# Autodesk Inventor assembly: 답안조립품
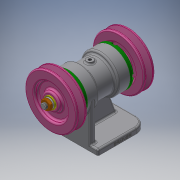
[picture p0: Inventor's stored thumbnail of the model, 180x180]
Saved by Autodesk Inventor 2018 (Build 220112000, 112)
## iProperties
Created: 2020-06
Part Number: 답안조립품
Material: 일반
Document SubType Name: Assembly
Designer: USER
Author: USER
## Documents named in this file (12)
- C:\Users\USER\Desktop\700606V1020\답안조립품.iam
- C:\Users\USER\Desktop\700606V1020\답안부품.ipt
- C:\Users\USER\Desktop\700606V1020\베어링 6204.ipt
- C:\Users\USER\Desktop\700606V1020\축.ipt
- C:\Users\USER\Desktop\700606V1020\커버.ipt
- C:\Users\USER\Desktop\700606V1020\오일 실 20 32 5.ipt
- C:\Users\USER\Desktop\700606V1020\Ű 5x5x12.ipt
- C:\Users\USER\Desktop\700606V1020\V-벨트풀리.ipt
- C:\Users\USER\Desktop\700606V1020\평면 와셔 10x21.ipt
- C:\Users\USER\Desktop\700606V1020\스프링 와셔 10.ipt
- C:\Users\USER\Desktop\700606V1020\너트 M10.ipt
- C:\Users\USER\Desktop\700606V1020\볼트 M4.ipt
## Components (4 placed, 2 different names)
1. Ű 5x5x12:1
2. Ű 5x5x12:2 — 각도:1
3. V-벨트풀리:1
4. V-벨트풀리:2
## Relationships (1: Angle 1)
- 각도:1 [Angle]: Ű 5x5x12:2
